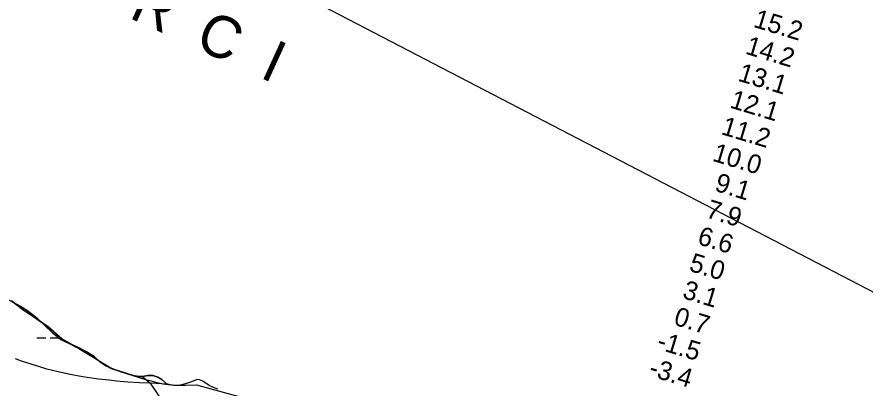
# Model space of a CAD drawing. Extents: x 3161514 to 3199414, y 831166 to 856601.
# Drawn here: x 3182577 to 3185603, y 851316 to 852641 of the extents above; entities that cross this region are included whole.
import ezdxf

# ---------------------------------------------------------------- set-up
doc = ezdxf.new("R2010")
doc.units = 0
for name, color, linetype in [('V-RIVR-IDEN', 7, 'Continuous'), ('V-RIVR-RANG', 7, 'Continuous'), ('V-SITE-VEGE', 7, 'Continuous'), ('V-TOPO-BNDY', 7, 'Continuous'), ('V-TOPO-SHOR', 7, 'Continuous'), ('V-WETL-SWMP', 7, 'Continuous')]:
    doc.layers.add(name, color=color, linetype=linetype)

msp = doc.modelspace()

# ---------------------------------------------------------------- linework, layer by layer
at = {"layer": 'V-SITE-VEGE'}
msp.add_lwpolyline([(3182526.6, 851641.6), (3182591.8, 851607), (3182618.5, 851590.1), (3182649.7, 851565.1), (3182675, 851540.3), (3182702.2, 851514.1), (3182734, 851489.7), (3182775.2, 851468.6), (3182801.9, 851454.4), (3182911.9, 851388.3), (3182942.1, 851376), (3182990.8, 851360.8), (3183032.5, 851347.3), (3183068.2, 851337.9), (3183097.4, 851330.7), (3183136.4, 851326.6), (3183179.6, 851325.7), (3183217.7, 851327.5), (3183238.5, 851321.4), (3183446.6, 851264)], dxfattribs=at)
at = {"layer": 'V-TOPO-BNDY'}
msp.add_line((3185799.4, 851570.6), (3179633.2, 854781.7), dxfattribs=at)
at = {"layer": 'V-TOPO-SHOR'}
msp.add_line((3183025.2, 851357.3), (3183052.2, 851332.9), dxfattribs=at)
for points in [[(3183025.2, 851357.3), (3183010.8, 851357.5), (3182992.1, 851360.9), (3182913.1, 851385.8), (3182895.7, 851395.4), (3182872.1, 851410.6), (3182852.1, 851428.4), (3182825.2, 851445.6), (3182798.6, 851459.2), (3182774.6, 851469.9), (3182736.8, 851491.7), (3182688.2, 851534.7), (3182653.6, 851558.9), (3182633.5, 851572.3), (3182613.8, 851586.1), (3182597.8, 851596.5), (3182558.1, 851627.1)], [(3183115.4, 851329.5), (3183110, 851331.3), (3183093.4, 851346.8), (3183080.2, 851354.8), (3183061.3, 851361.1), (3183044.4, 851361.1), (3183025.2, 851357.3)], [(3183052.2, 851332.9), (3183099.9, 851263.2), (3183100.4, 851262.1), (3183127.8, 851235.5), (3183165.7, 851220.4), (3183207, 851208.8), (3183259.6, 851191.5), (3183308.3, 851170.8), (3183347.9, 851159.3), (3183369.9, 851148.8), (3183390.5, 851122.7), (3183404.1, 851098)], [(3183293.5, 851312.1), (3183278.6, 851317.9), (3183262.8, 851325.2), (3183240.2, 851340.1), (3183228, 851345.2), (3183218.5, 851346.4), (3183206, 851340.9), (3183189.1, 851334.5), (3183160.5, 851325.9), (3183141.9, 851325.1), (3183123.1, 851326.9), (3183115.4, 851329.5)]]:
    msp.add_lwpolyline(points, dxfattribs=at)
at = {"layer": 'V-WETL-SWMP'}
for p, q in [((3182647.9, 851495.1), (3182679.9, 851495.1)), ((3182695.9, 851495), (3182727.9, 851494.9))]:
    msp.add_line(p, q, dxfattribs=at)
for points in [[(3182558.1, 851627.1), (3182597.8, 851596.5), (3182613.8, 851586.1), (3182633.5, 851572.3), (3182653.6, 851558.9), (3182688.2, 851534.7), (3182736.8, 851491.7), (3182774.6, 851469.9), (3182798.7, 851459.2)], [(3182798.7, 851459.2), (3182825.2, 851445.6), (3182852.1, 851428.4), (3182872.1, 851410.6), (3182895.7, 851395.4), (3182913.1, 851385.8), (3182992.1, 851360.9), (3183010.8, 851357.5), (3183025.2, 851357.2), (3183044.4, 851361.1), (3183061.3, 851361.1), (3183080.2, 851354.8), (3183093.4, 851346.8), (3183110, 851331.3), (3183115.4, 851329.5)], [(3183115.4, 851329.5), (3183052.2, 851332.9), (3183014.3, 851334.9), (3182973, 851337.5), (3182931.9, 851340.9), (3182904.5, 851343.6), (3182868, 851348), (3182819.6, 851355.1), (3182792, 851359.8), (3182760.5, 851365.9), (3182724.6, 851373.8), (3182683.7, 851384), (3182662, 851390.1), (3182627.5, 851400.7), (3182593.7, 851412.5), (3182571.4, 851420.9)]]:
    msp.add_lwpolyline(points, dxfattribs=at)

# ---------------------------------------------------------------- texts
at = {"layer": 'V-RIVR-IDEN'}
msp.add_text('R  A  C  C  O  U  R  C  I', height=150, rotation=335.471, dxfattribs=at).set_placement((3181573.9, 853278.1))
at = {"layer": 'V-RIVR-RANG'}
for s, p in [('15.2', (3185201.2, 852606.4)), ('14.2', (3185172.5, 852510.6)), ('13.1', (3185146, 852414.1)), ('12.1', (3185117.2, 852318.3)), ('11.2', (3185086.2, 852223.3)), ('10.0', (3185054.7, 852128.3)), ('9.1', (3185062.8, 852021.4)), ('7.9', (3185031.5, 851926.4)), ('6.6', (3185001.3, 851831)), ('5.0', (3184971.5, 851735.6)), ('3.1', (3184947.8, 851638.3)), ('0.7', (3184916.8, 851543.2)), ('-1.5', (3184856.2, 851457)), ('-3.4', (3184827.5, 851361.2))]:
    msp.add_text(s, height=67, rotation=343.1483, dxfattribs=at).set_placement(p)

doc.saveas('drawing.dxf')
